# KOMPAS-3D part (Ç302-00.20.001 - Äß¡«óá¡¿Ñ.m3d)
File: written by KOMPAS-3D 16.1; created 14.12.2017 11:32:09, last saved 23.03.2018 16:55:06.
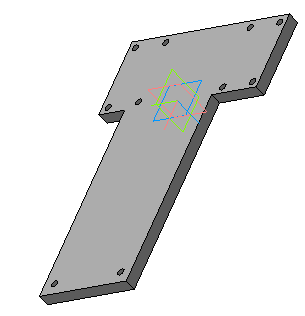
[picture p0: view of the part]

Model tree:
1. Эскиз:1
2. Операция выдавливания:1
     Расстояние 1 = 15
3. Эскиз:4
4. Вырезать элемент выдавливания:2
     Расстояние 1 = 15
5. Массив по сетке:1  (with: Вырезать элемент выдавливания:2, Эскиз:4)  (2 pattern instances)
     Наклон = 90; Шаг 1 = 102; Угол раствора = 90; Номер 1 = 1
6. Эскиз:5
7. Операция выдавливания:2
     Расстояние 1 = 144.5; Расстояние 2 = 15
8. Эскиз:6
9. Вырезать элемент выдавливания:3
     Расстояние 1 = 15
10. Эскиз:7
11. Операция выдавливания:3
     Расстояние 1 = 144.5; Расстояние 2 = 15
12. Скругление:1
     Радиус = 10
13. Фаска:2
     Угол = 45; Длина 1 = 1; Длина 2 = 1
14. Эскиз:2
15. Отверстие:1
     Глубина выреза = 15; Диаметр отверстия = 6; Угол конуса торца = 118; Координата X = -95; Координата Y = 12; Диаметр цековки/зенковки = 7.6; Глубина цековки = 8; Угол зенковки = 90
16. Эскиз:3
17. Вырезать элемент выдавливания:1
     Расстояние 1 = 15
18. Средняя плоскость:1
19. Зеркальный массив:1
20. Экземпляр ( 1 )
21. Экземпляр ( 2 )  (with: Вырезать элемент выдавливания:1)  (labels: Полипропилен  ГОСТ 26996-86)

Expressions: 26+3; 250+16
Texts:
  Body Specification ( left align )
  Body Specificaton ( centered )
